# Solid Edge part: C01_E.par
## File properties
Author: edge
Template: Normal.par
Last saved by: edge
Revision: 12
Application: Solid Edge
Accuracy: 0.990
文書内容のタイプ: 0
面のスタイル: Yellow
Coef. of Thermal Exp: 0.0
Thermal Conductivity: 0.0
Specific Heat: 0.0
Modulus of Elasticity: 0.0
Poission's Ratio: 0.0
Yield Stress: 0.0
Ultimate Stress: 0.0
Elongation: 0.0
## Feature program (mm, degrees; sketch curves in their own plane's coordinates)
sketch for "unnamed Protrusion 1" plane through (0, 0, 0) normal (0, 0, 1) x-axis (1, 0, 0)
  line (-20, -40) -> (20, -40)
  line (20, -40) -> (20, 40)
  line (20, 40) -> (-20, 40)
  line (-20, 40) -> (-20, -40)
  dimension (linear) = 20
  dimension (linear) = 20
extrude "unnamed Protrusion 1" add finite 40 along +normal
sketch for "unnamed Cutout 1" plane through (0, 0, 0) normal (1, 0, 0) x-axis (0, 1, 0)
  line (0, 0) -> (0, 0)
  line (-20, 45) -> (-20, 15)
  line (-20, 15) -> (43.12, 15)
  line (43.12, 15) -> (43.12, 45)
  line (43.12, 45) -> (-20, 45)
  dimension (linear) = 43.12
  dimension (linear) = 43.12
extrude "unnamed Cutout 1" cut through
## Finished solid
Body 1: solid body, 8 faces, 18 edges, 12 vertices.
  Faces by surface: plane 8
  Edges by curve: line 18
Bounding box of the edges (mm): 40.000 x 80.000 x 40.000, from (-20, -40, 0) to (20, 40, 40).
Planar faces by outward normal: +x 1, +y 2, +z 2, -x 1, -y 1, -z 1
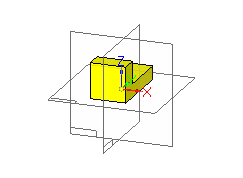
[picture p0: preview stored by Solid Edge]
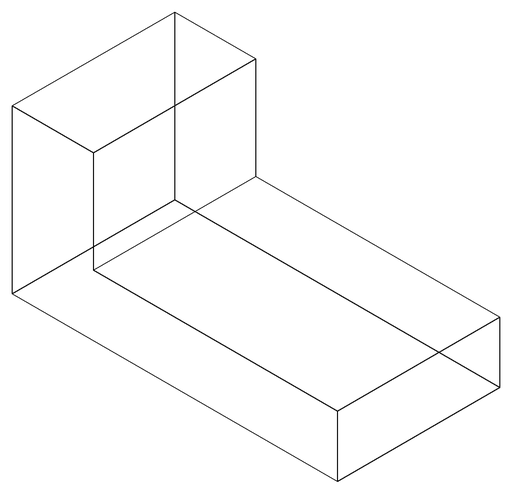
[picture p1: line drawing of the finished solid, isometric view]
